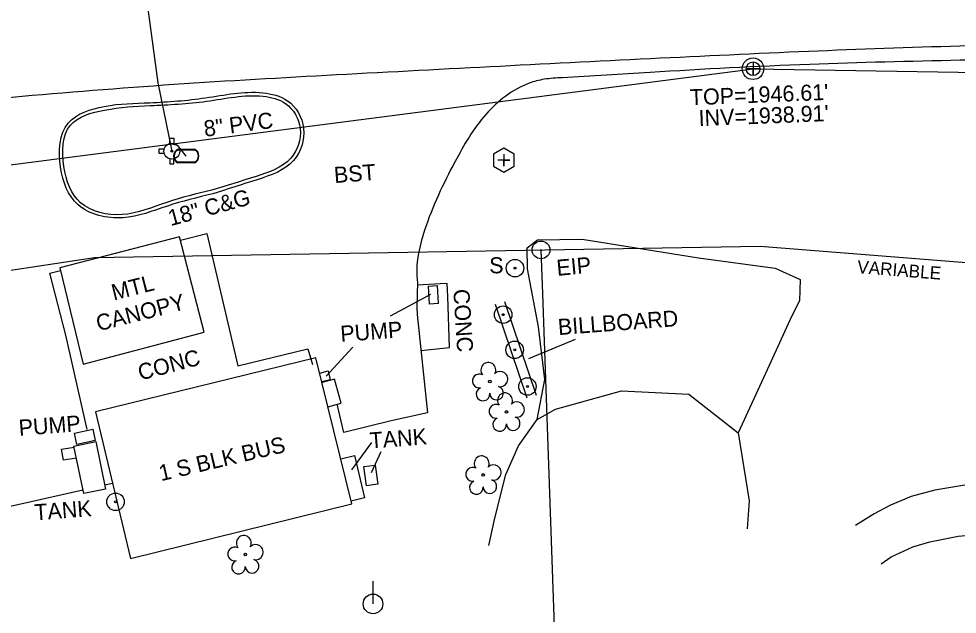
# Model space of a CAD drawing. Extents: x 553786 to 558838, y 502329 to 507342.
# Drawn here: x 554413 to 554646.7, y 502913.8 to 503062.1 of the extents above; entities that cross this region are included whole.
import ezdxf

# ---------------------------------------------------------------- set-up
doc = ezdxf.new("R2010")
doc.units = 0
for name, color, linetype in [('Exist Building Metal Canopy Text', 7, 'Continuous'), ('Exist Building Text', 7, 'Continuous'), ('Exist Other Culture AG Tank', 7, 'Continuous'), ('Exist Other Culture AG Tank Leader', 7, 'Continuous'), ('Exist Other Culture AG Tank Text', 7, 'Continuous'), ('Exist Other Culture Area Outline Text', 7, 'Continuous'), ('Exist Other Culture Gas Pump Island', 7, 'Continuous'), ('Exist Other Culture Gas Pump Island Leader', 7, 'Continuous'), ('Exist Other Culture Gas Pump Island Text', 7, 'Continuous'), ('Exist Other Culture Sign', 7, 'Continuous'), ('Exist Other Culture Sign Leader', 7, 'Continuous'), ('Exist Other Culture Sign Post Text', 7, 'Continuous'), ('Exist Other Culture Sign Text', 7, 'Continuous'), ('Exist Property Iron Pin Text', 7, 'Continuous'), ('Exist Right of Way Line Text', 7, 'Continuous'), ('Exist Roads Change in Surface Text', 7, 'Continuous'), ('Exist Roads EOP Text', 7, 'Continuous'), ('Exist Utilities Other Located Object CELL', 7, 'Continuous'), ('Exist Utilities Sanitary Sewer Manhole Text', 7, 'Continuous'), ('Exist Utilities Sanitary Sewer UG Line', 7, 'Continuous'), ('Exist Utilities Sanitary Sewer UG Line Invert Elevation', 7, 'Continuous'), ('Exist Utilities Sanitary Sewer UG Line Text', 7, 'Continuous'), ('Exist Vegetation Hedge Row', 7, 'Continuous'), ('Exist Vegetation Tree CELL', 7, 'Continuous'), ('Exist Vegetation Woods Line', 7, 'Continuous'), ('Prop Conc Barrier Precast Reinforced Single Face', 7, 'Continuous'), ('Prop Drainage Structure Catch Basin Grate 840 03F Label', 7, 'Continuous'), ('Prop Drainage Structure Drop Inlet Grate 840 16 Label', 7, 'Continuous'), ('Prop Drainage Structure Headwall CELL', 7, 'Continuous'), ('Prop Drainage Structure Junction Box with Manhole Label', 7, 'Continuous'), ('Prop Drainage Structure Pipe Alternate 24in', 7, 'Continuous'), ('Prop Drainage Structure Pipe Alternate 36in', 7, 'Continuous'), ('Prop Drainage Structure Pipe RCP 15in Class III Label', 7, 'Continuous'), ('Prop Drainage Structure Pipe RCP 15in Class IV', 7, 'Continuous'), ('Prop Drainage Structure Pipe RCP 30in Class III Label', 7, 'Continuous'), ('Prop Drainage Structure Pipe RCP 42in Class III Label', 7, 'Continuous'), ('Prop Drainage Structure Plot Symbol 50 Scale', 7, 'Continuous'), ('Prop Drainage Structure Tops and Inverts LABEL', 7, 'Continuous'), ('Prop Earthen Structure Tail Ditch Label', 7, 'Continuous'), ('Prop Earthen Structure V Ditch Lateral Detail Label', 7, 'Continuous'), ('Prop Erosion Rip Rap Pad Outlet for Jurisdictional Stream CELL', 7, 'Continuous'), ('Prop Plan Preparation Cover Label', 7, 'Continuous'), ('Prop Plan Preparation Table Ditch Data CELL', 7, 'Continuous'), ('Prop XS SE Text', 7, 'Continuous'), ('Sheet Layout Plan Border', 7, 'Continuous')]:
    doc.layers.add(name, color=color, linetype=linetype)

# ---------------------------------------------------------------- blocks, each defined once
blk = doc.blocks.new('EXIST UTILITIES WATER FIRE HYDRANT')
at = {"layer": 'Prop Drainage Structure Junction Box with Manhole Label'}
blk.add_line((0, 0), (0, 0), dxfattribs=at)
for points in [[(-0.01025, 0.03825), (-0.01025, 0.064), (0.01025, 0.064), (0.01025, 0.03775)], [(-0.03825, 0.01025), (-0.064, 0.01025), (-0.064, -0.01025), (-0.03825, -0.01025)], [(-0.01025, -0.03825), (-0.01025, -0.064), (0.01025, -0.064), (0.01025, -0.03775)]]:
    blk.add_lwpolyline(points, dxfattribs=at)
for radius in [0.03954, 0.00485]:
    blk.add_circle((0, 0), radius, dxfattribs=at)
blk = doc.blocks.new('EXIST UTILITIES WATER METER')
at = {"layer": 'Prop Drainage Structure Drop Inlet Grate 840 16 Label'}
blk.add_line((0, 0), (0, 0), dxfattribs=at)
for points in [[(-0.0408, 0.034), (0.0408, 0.034)], [(-0.0408, 0.0312), (0.0408, 0.0312)], [(0.0408, -0.0312), (-0.0413, -0.0312)], [(0.0408, -0.034), (-0.0413, -0.034)]]:
    blk.add_lwpolyline(points, dxfattribs=at)
for centre, radius, start, end in [((-0.0261, -0.0001), 0.0371, 113.178, 245.9794), ((-0.0259, -0.0001), 0.0347, 115.3009, 243.7824), ((0.0259, 0), 0.0371, 293.6483, 66.3084), ((0.0261, 0), 0.0345, 295.1272, 64.8728)]:
    blk.add_arc(centre, radius, start, end, dxfattribs=at)
blk = doc.blocks.new('EXIST UTILITIES SANITARY SEWER CLEAN-OUT')
at = {"layer": 'Prop Drainage Structure Pipe RCP 30in Class III Label'}
blk.add_line((0, 0), (0, 0), dxfattribs=at)
blk.add_lwpolyline([(-0.0516, 0.0299), (-0.0517, -0.0297), (-0.0001, -0.0596), (0.0516, -0.0299), (0.0517, 0.0297), (0.0001, 0.0596)], close=True, dxfattribs=at)
blk.add_lwpolyline([(0, 0.0302), (0, -0.0302), (0, 0), (0.0302, 0), (-0.0302, 0)], dxfattribs=at)
blk = doc.blocks.new('EXIST UTILITIES SANITARY SEWER MANHOLE')
at = {"layer": 'Prop Drainage Structure Catch Basin Grate 840 03F Label'}
blk.add_lwpolyline([(0, 0.03425), (0, -0.03425), (0, 0), (0.03425, 0), (-0.03425, 0)], dxfattribs=at)
for radius in [0.05389, 0.03425]:
    blk.add_circle((0, 0), radius, dxfattribs=at)
blk = doc.blocks.new('EXIST PROPERTY IRON PIN')
at = {"layer": 'Prop Drainage Structure Pipe RCP 15in Class IV'}
for radius in [0.0441, 0.00141]:
    blk.add_circle((0, 0), radius, dxfattribs=at)

msp = doc.modelspace()

# ---------------------------------------------------------------- linework, layer by layer
at = {"layer": 'Exist Other Culture AG Tank'}
for points in [[(554490.02, 502965.49), (554493.28, 502966.37), (554491.65, 502972.41), (554488.54, 502971.57)], [(554493.19, 502952.56), (554496.6, 502953.37), (554499.13, 502942.8), (554495.78, 502942)]]:
    msp.add_lwpolyline(points, dxfattribs=at)
for points in [[(554432.18, 502956.86), (554434.66, 502944.99), (554429.21, 502943.86), (554426.74, 502955.72)], [(554499.58, 502945.85), (554498.97, 502950.61), (554501.81, 502950.98), (554502.42, 502946.22)]]:
    msp.add_lwpolyline(points, close=True, dxfattribs=at)
at = {"layer": 'Exist Other Culture AG Tank Leader'}
for p, q in [((554495.96, 502949.78), (554500.98, 502956.58)), ((554500.87, 502949.14), (554503.3, 502954.39))]:
    msp.add_line(p, q, dxfattribs=at)
at = {"layer": 'Exist Other Culture Gas Pump Island'}
for points in [[(554515.31, 502991.07), (554515.03, 502995.55), (554517.19, 502995.68), (554517.47, 502991.2)], [(554426.89, 502958.89), (554431.47, 502959.89), (554432.07, 502957.14), (554427.49, 502956.14)]]:
    msp.add_lwpolyline(points, close=True, dxfattribs=at)
msp.add_lwpolyline([(554487.97, 502973.89), (554490.03, 502974.42), (554490.59, 502972.22), (554488.51, 502971.68)], dxfattribs=at)
at = {"layer": 'Exist Other Culture Gas Pump Island Leader'}
for p, q in [((554515.55, 502993.45), (554505.48, 502988.03)), ((554489.54, 502973.11), (554496.23, 502980.34))]:
    msp.add_line(p, q, dxfattribs=at)
at = {"layer": 'Exist Other Culture Sign'}
for points in [[(554539.6, 502967.62), (554531.74, 502990.94)], [(554533.99, 502991.7), (554541.84, 502968.37)]]:
    msp.add_lwpolyline(points, dxfattribs=at)
at = {"layer": 'Exist Other Culture Sign Leader'}
msp.add_line((554540.03, 502977.49), (554551.69, 502982.38), dxfattribs=at)
at = {"layer": 'Exist Utilities Other Located Object CELL'}
for radius in [2.18, 0.24]:
    msp.add_circle((554437.12, 502941.84), radius, dxfattribs=at)
at = {"layer": 'Exist Utilities Sanitary Sewer UG Line'}
for p, q in [((554351.98, 503018.13), (554595.87, 503049.7)), ((554595.87, 503049.7), (554988.9, 503043.34))]:
    msp.add_line(p, q, dxfattribs=at)
at = {"layer": 'Exist Vegetation Hedge Row'}
msp.add_lwpolyline([(554542.09, 502962.34), (554544.04, 502972.32), (554542.49, 502985.41), (554539.75, 502999.83), (554539.64, 503005.06), (554542.19, 503007.11), (554553.34, 503007.21), (554582.32, 503002.62), (554601.37, 503000.01), (554607.58, 502997.24), (554607.41, 502991.91), (554605.53, 502988.15), (554599, 502973.81), (554592.18, 502959.04)], dxfattribs=at)
at = {"layer": 'Exist Vegetation Tree CELL'}
for p, q in [((554530.34, 502971.8), (554530.34, 502971.8)), ((554534.48, 502964.21), (554534.48, 502964.21)), ((554528.68, 502948.52), (554528.68, 502948.52)), ((554469.44, 502928.69), (554469.44, 502928.69))]:
    msp.add_line(p, q, dxfattribs=at)
for centre in [(554530.34, 502971.8), (554534.48, 502964.21), (554528.68, 502948.52), (554469.44, 502928.69)]:
    msp.add_circle(centre, 0.326, dxfattribs=at)
for centre, radius, start, end in [((554529.95, 502974.67), 1.86, 330.1651, 219.7134), ((554532.89, 502972.39), 1.9, 257.1011, 134.1999), ((554527.73, 502971.95), 1.73, 62.6636, 279.3457), ((554528.63, 502968.68), 1.69, 111.5671, 6.231), ((554532.01, 502968.9), 1.7, 181.2822, 74.56), ((554534.1, 502967.08), 1.86, 330.1651, 219.7134), ((554531.88, 502964.36), 1.73, 62.6636, 279.3457), ((554537.03, 502964.8), 1.9, 257.1011, 134.1999), ((554532.78, 502961.09), 1.69, 111.5671, 6.231), ((554536.16, 502961.31), 1.7, 181.2822, 74.56), ((554528.29, 502951.4), 1.86, 330.1651, 219.7134), ((554531.23, 502949.11), 1.9, 257.1011, 134.1999), ((554526.07, 502948.68), 1.73, 62.6636, 279.3457), ((554526.97, 502945.4), 1.69, 111.5671, 6.231), ((554530.35, 502945.63), 1.7, 181.2822, 74.56), ((554469.06, 502931.56), 1.86, 330.1651, 219.7134), ((554466.83, 502928.84), 1.73, 62.6636, 279.3457), ((554471.99, 502929.28), 1.9, 257.1011, 134.1999), ((554467.74, 502925.57), 1.69, 111.5671, 6.231), ((554471.11, 502925.79), 1.7, 181.2822, 74.56)]:
    msp.add_arc(centre, radius, start, end, dxfattribs=at)
at = {"layer": 'Exist Vegetation Woods Line'}
msp.add_lwpolyline([(554530.11, 502930.97), (554531.54, 502937.77), (554534.28, 502948.63), (554537.47, 502955.78), (554542.09, 502962.34), (554546.71, 502964.87), (554563.1, 502969.51), (554579.89, 502968.63), (554592.18, 502959.04), (554594.89, 502942.09), (554594.41, 502935.09)], dxfattribs=at)
at = {"layer": 'Prop Conc Barrier Precast Reinforced Single Face'}
for centre, radius in [((554536.6, 503000.01), 2.18), ((554536.6, 503000.01), 0.24), ((554533.65, 502988.44), 2.18), ((554533.65, 502988.44), 0.24), ((554536.52, 502979.67), 2.18), ((554536.52, 502979.67), 0.24), ((554539.69, 502970.54), 2.18), ((554539.69, 502970.54), 0.24)]:
    msp.add_circle(centre, radius, dxfattribs=at)
at = {"layer": 'Prop Drainage Structure Headwall CELL'}
msp.add_spline([(555002.05, 503041.83), (554964.24, 503045.65), (554925.55, 503048.89), (554886.08, 503051.15), (554847.29, 503053.26), (554810.28, 503054.49), (554766.79, 503055.75), (554727.94, 503056.26), (554687.99, 503056.08), (554647.36, 503055.32), (554609.74, 503053.99), (554570.3, 503052.17), (554530.42, 503050.16), (554489.62, 503048), (554449.13, 503045.57), (554408.82, 503042.34), (554368.28, 503038.73), (554338.38, 503036.05)], degree=3, dxfattribs=at)
at = {"layer": 'Prop Drainage Structure Pipe Alternate 24in'}
for points in [[(554444.56, 503069.03), (554447.61, 503046.21), (554451.12, 503029.19)], [(554454.72, 503027.94), (554452.64, 503030.58), (554450.6, 503031.03)], [(554454.72, 503027.94), (554452.64, 503030.58), (554450.6, 503031.03)]]:
    msp.add_lwpolyline(points, dxfattribs=at)
at = {"layer": 'Prop Drainage Structure Pipe Alternate 36in'}
for points in [[(554768.82, 503005.87), (554768.58, 503023.49), (554765.24, 503037.54), (554758.19, 503048.88), (554755.44, 503051.39), (554752.27, 503052.18), (554728.16, 503052.54), (554688.05, 503052.36), (554647.46, 503051.79), (554610, 503050.78), (554570.22, 503048.76), (554548.38, 503047.45), (554543.86, 503047.06), (554540.14, 503046.08), (554529.32, 503038.3), (554521.66, 503026.55), (554514.08, 503009.49), (554512.17, 502997.84), (554512.28, 502996.65)], [(554461.31, 503018.55), (554472.4, 503022.06), (554481.44, 503026.81), (554483.96, 503034.85), (554479.97, 503041.71), (554473.77, 503043.71), (554459.55, 503042.45), (554445.65, 503041.24), (554434.32, 503040.32), (554425.35, 503036.16), (554423.4, 503025.18), (554427.79, 503015.82), (554438.93, 503012.58), (554450.02, 503015.48), (554461.31, 503018.55)]]:
    msp.add_spline(points, degree=3, dxfattribs=at)
at = {"layer": 'Prop Drainage Structure Pipe RCP 15in Class III Label'}
for p, q in [((554431.84, 503002.7), (554597.66, 503005.49)), ((554597.66, 503005.49), (555158.9, 502961.45)), ((554282.41, 502980.21), (554431.84, 503002.7))]:
    msp.add_line(p, q, dxfattribs=at)
at = {"layer": 'Prop Drainage Structure Pipe RCP 42in Class III Label'}
for points in [[(554453.26, 503006.97), (554459.86, 503008.64), (554467.58, 502975.69), (554484.99, 502979.94), (554486.13, 502976.01)], [(554430.07, 502959.85), (554424.74, 502983.35), (554420.79, 502998.77), (554423.42, 502999.43)]]:
    msp.add_lwpolyline(points, dxfattribs=at)
at = {"layer": 'Prop Drainage Structure Plot Symbol 50 Scale'}
for points in [[(554366.41, 503004.93), (554367.54, 503004.14), (554373.31, 502983.9), (554371.28, 502978.48), (554372.42, 502971.74), (554372.92, 502967.35), (554373.98, 502965.65), (554375.43, 502964.47), (554377.48, 502963.24), (554372.66, 502961.17), (554379.61, 502942.41), (554388.54, 502945.31), (554391.35, 502938.82), (554394.12, 502938.62), (554401.45, 502938.68), (554413.53, 502941.34), (554429.01, 502944.85)], [(554512.28, 502996.65), (554512.16, 502990.23), (554512.23, 502988.49), (554514.78, 502964.03), (554505.72, 502962.03), (554493.97, 502959.1), (554492.34, 502966.12)], [(554434.43, 502946.08), (554436.34, 502946.51)]]:
    msp.add_lwpolyline(points, dxfattribs=at)
at = {"layer": 'Prop Drainage Structure Tops and Inverts LABEL'}
msp.add_spline([(554461.09, 503019.46), (554472.11, 503022.87), (554480.74, 503027.39), (554483.13, 503034.77), (554479.43, 503041.03), (554473.89, 503042.84), (554459.8, 503041.59), (554445.75, 503040.51), (554434.35, 503039.41), (554425.89, 503035.64), (554424.25, 503025.35), (554428.4, 503016.33), (554438.75, 503013.36), (554449.92, 503016.42), (554461.09, 503019.46)], degree=3, dxfattribs=at)
at = {"layer": 'Prop Earthen Structure Tail Ditch Label'}
for points in [[(554513.16, 502979.52), (554520.32, 502980.25), (554519.91, 502992.94), (554519.73, 502996.21), (554517.96, 502996.09), (554512.21, 502995.78)], [(554427.36, 502952.73), (554424.15, 502952.18), (554423.63, 502954.94), (554426.79, 502955.48)]]:
    msp.add_lwpolyline(points, dxfattribs=at)
at = {"layer": 'Prop Earthen Structure V Ditch Lateral Detail Label'}
for points in [[(554753.61, 502954.6), (554731.11, 502950.48), (554706, 502947.99), (554690.33, 502947.66), (554668.57, 502947.22), (554651.08, 502946.35), (554641.16, 502944.7), (554635.28, 502943.12), (554630.09, 502941), (554626.01, 502938.8), (554621.36, 502935.91)], [(554627.75, 502926.42), (554630.24, 502928.1), (554635.7, 502930.58), (554639.9, 502931.86), (554646.96, 502933.26), (554658.78, 502934.32), (554670.47, 502934.58), (554694.99, 502935.33), (554711.37, 502936.6), (554729.17, 502937.86), (554746.77, 502941.71), (554759.17, 502944.14), (554761.75, 502942.96)]]:
    msp.add_lwpolyline(points, dxfattribs=at)
at = {"layer": 'Prop Erosion Rip Rap Pad Outlet for Jurisdictional Stream CELL'}
msp.add_lwpolyline([(554440.85, 502927.68), (554495.95, 502941.32), (554487.03, 502977.72), (554432.09, 502964.28)], close=True, dxfattribs=at)
at = {"layer": 'Prop Plan Preparation Cover Label'}
for q in [(554501.24, 502922.03), (554501.24, 502916.4)]:
    msp.add_line((554501.24, 502916.4), q, dxfattribs=at)
msp.add_circle((554501.24, 502916.4), 2.45, dxfattribs=at)
at = {"layer": 'Prop Plan Preparation Table Ditch Data CELL'}
msp.add_lwpolyline([(554429.05, 502976.09), (554459.22, 502984.1), (554453.05, 503007.79), (554423.25, 503000.13)], close=True, dxfattribs=at)
at = {"layer": 'Prop XS SE Text'}
for p, q in [((554543.07, 503004.57), (554543.46, 502993.59)), ((554543.46, 502993.59), (554550.7, 502788.23))]:
    msp.add_line(p, q, dxfattribs=at)
at = {"layer": 'Sheet Layout Plan Border'}
msp.add_arc((554712.36, 500222.83), 2864.79, 70.63346, 92.31986, dxfattribs=at)

# ---------------------------------------------------------------- block references
at = {"layer": 'Prop Drainage Structure Catch Basin Grate 840 03F Label', "xscale": 50, "yscale": 50}
msp.add_blockref('EXIST UTILITIES SANITARY SEWER MANHOLE', (554595.87, 503049.7), dxfattribs=at)
at = {"layer": 'Prop Drainage Structure Drop Inlet Grate 840 16 Label', "xscale": 50, "yscale": 50}
msp.add_blockref('EXIST UTILITIES WATER METER', (554454.73, 503027.95), dxfattribs=at)
at = {"layer": 'Prop Drainage Structure Junction Box with Manhole Label', "xscale": 50, "yscale": 50}
msp.add_blockref('EXIST UTILITIES WATER FIRE HYDRANT', (554451.14, 503029.17), dxfattribs=at)
at = {"layer": 'Prop Drainage Structure Pipe RCP 15in Class IV', "xscale": 50, "yscale": 50}
msp.add_blockref('EXIST PROPERTY IRON PIN', (554543.07, 503004.57), dxfattribs=at)
at = {"layer": 'Prop Drainage Structure Pipe RCP 30in Class III Label', "xscale": 50, "yscale": 50}
msp.add_blockref('EXIST UTILITIES SANITARY SEWER CLEAN-OUT', (554533.8, 503026.93), dxfattribs=at)

# ---------------------------------------------------------------- texts
at = {"layer": 'Exist Building Metal Canopy Text'}
for s, p in [('MTL', (554436.68, 502991.96)), ('CANOPY', (554432.85, 502984.28))]:
    msp.add_text(s, height=4, rotation=14.26, dxfattribs=at).set_placement(p)
at = {"layer": 'Exist Building Text'}
msp.add_text('1 S BLK BUS', height=4, rotation=13.1985, dxfattribs=at).set_placement((554448.44, 502946.95))
at = {"layer": 'Exist Other Culture AG Tank Text'}
for p in [(554500.56, 502955.09), (554417.06, 502937.2)]:
    msp.add_text('TANK', height=4, rotation=4.3199, dxfattribs=at).set_placement(p)
at = {"layer": 'Exist Other Culture Area Outline Text'}
msp.add_text('CONC', height=4, rotation=273.6975, dxfattribs=at).set_placement((554521.21, 502994.71))
at = {"layer": 'Exist Other Culture Gas Pump Island Text'}
for p in [(554493.25, 502981.65), (554413.15, 502958.26)]:
    msp.add_text('PUMP', height=4, rotation=4.3199, dxfattribs=at).set_placement(p)
at = {"layer": 'Exist Other Culture Sign Post Text'}
msp.add_text('S', height=4, dxfattribs=at).set_placement((554530.18, 502998.74))
at = {"layer": 'Exist Other Culture Sign Text'}
msp.add_text('BILLBOARD', height=4, rotation=4.3199, dxfattribs=at).set_placement((554547.43, 502983.35))
at = {"layer": 'Exist Property Iron Pin Text'}
msp.add_text('EIP', height=4, rotation=5.3199, dxfattribs=at).set_placement((554547.12, 502998.09))
at = {"layer": 'Exist Right of Way Line Text'}
msp.add_text('VARIABLE', height=3.2, rotation=355.5134, dxfattribs=at).set_placement((554621.73, 502998.79))
at = {"layer": 'Exist Roads Change in Surface Text'}
msp.add_text('CONC', height=4, rotation=14.7636, dxfattribs=at).set_placement((554443.3, 502972.02))
at = {"layer": 'Exist Roads EOP Text'}
for s, rotation, p in [('BST', 4.3199, (554491.66, 503021.22)), ('18" C&G', 15.2049, (554450.84, 503010.48))]:
    msp.add_text(s, height=4, rotation=rotation, dxfattribs=at).set_placement(p)
at = {"layer": 'Exist Utilities Sanitary Sewer Manhole Text'}
msp.add_text("TOP=1946.61'", height=4, rotation=2.2794, dxfattribs=at).set_placement((554580.24, 503040.57))
at = {"layer": 'Exist Utilities Sanitary Sewer UG Line Invert Elevation'}
msp.add_text("INV=1938.91'", height=4, rotation=2.2794, dxfattribs=at).set_placement((554582.4, 503035.38))
at = {"layer": 'Exist Utilities Sanitary Sewer UG Line Text'}
msp.add_text('8" PVC', height=4, rotation=7.3754, dxfattribs=at).set_placement((554459.36, 503032.74))

doc.saveas('drawing.dxf')
